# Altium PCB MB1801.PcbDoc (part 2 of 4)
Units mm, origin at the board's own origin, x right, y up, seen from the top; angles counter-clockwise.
Board outline 70.1 x 57.1 mm, 4 copper layers (Top Layer, Signal Layer 1, Signal Layer 2, Bottom Layer), stack 1.614 mm thick; 219 components, 166 nets, 1002 pads, 473 vias.
Unrouted connection lines stored in the file: 2.
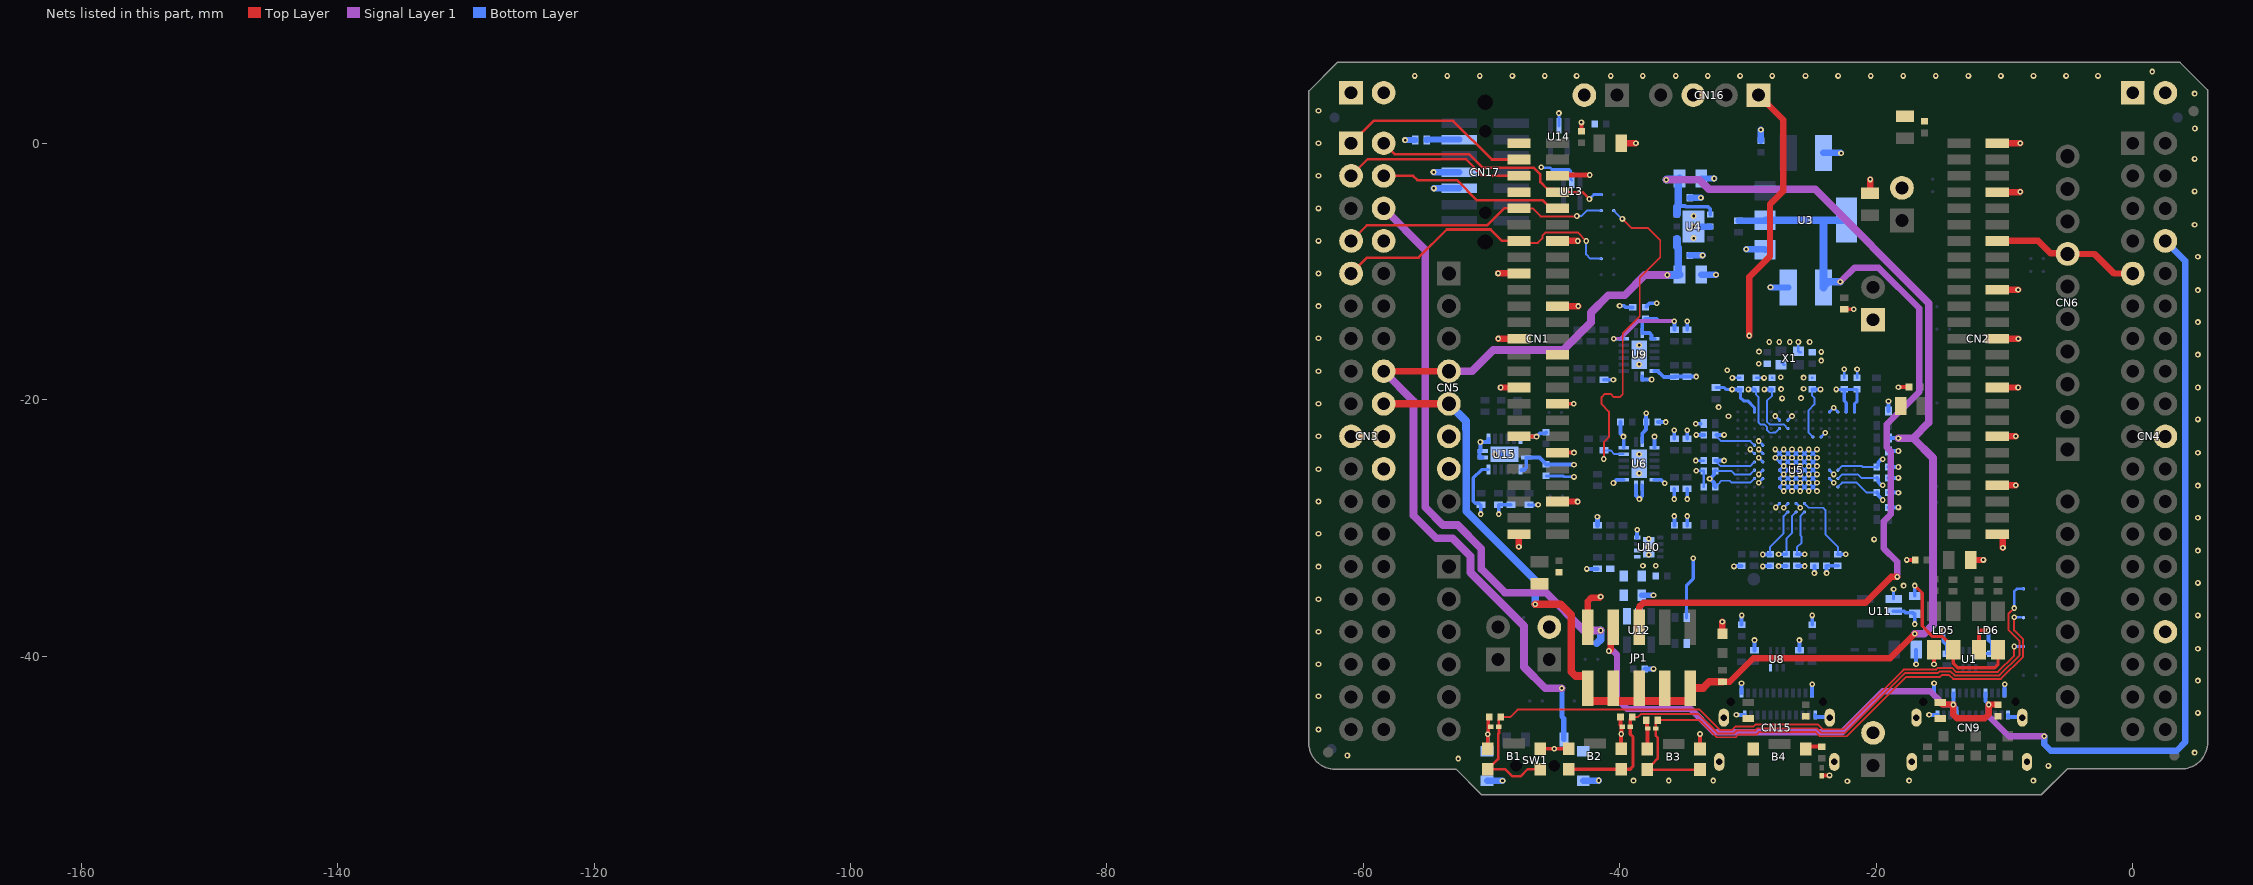
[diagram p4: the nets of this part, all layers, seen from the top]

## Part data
1 ?: library part MCD-01965
B1 B2 B3 B4: library part MCD-01485, "Microminiature Tact Switch for SMT - KMR 2 Series - 1.9 mm height", Manufacturer=C&K, Manufacturer_Part_Number=KMR231GLFS
C1 C2 C3 C4 C5 C6 C19 C21: library part MCD-01550, "Capacitor, MLCC, 1uF, 16V, X5R, +/-10%, 0805, T=0.85mm", Manufacturer=YAGEO, Manufacturer_Part_Number=CC0805KRX5R7BB105, Package=0805
C7 C8 C9 C10 C11 C18 C20 C22 C35 C58: library part MCD-02355, "Capacitor, MLCC, 100nF, 25V, X7R, +/-10%, 0402, T=0.5mm", Manufacturer=WALSIN, Manufacturer_Part_Number=0402B104K250CT, Package=0402
C12 C13 C14 C26 C27 C36: library part MCD-02198, "Capacitor, MLCC, 10nF, 50V, X7R, +/-10%, 0402, T=0.5mm", Manufacturer=YAGEO, Manufacturer_Part_Number=CC0402KRX7R9BB103, Package=0402
C15 C23: library part MCD-00205, "Capacitor, MLCC, 100pF, 50V, NPO, +/-5%, 0402, T=0.5mm", Manufacturer=YAGEO, Manufacturer_Part_Number=CC0402JRNPO9BN101, Package=0402
C16 C17: library part MCD-00324, "Capacitor, Tantalum, 10uF, 25V, 2R5, +/-10%, Type_B (3528 metric), T=1.9mm", Manufacturer=AVX, Manufacturer_Part_Number=TAJB106K025RNJ, Package="3528 (metric)"
C24 C25 C30 C31 C32 C37 C38 C39 C40 C41 C42 C43 C44 C45 C46 C47 C48 C49 C50 C51 C52 C53 C60 C61 C62: library part MCD-00006, "Capacitor, MLCC, 100nF, 16V, X7R, 10%, 0402, T=0.5mm", Alternate_Manufacturer=MURATA, Alternate_Manufacturer_Part_Number=GCM155R71C104KA55D, Manufacturer=YAGEO, Manufacturer_Part_Number=CC0402KRX7R7BB104, Package=C0402
C28 C29: library part MCD-01774, "Capacitor, MLCC, 2.7pF, 50V, NPO, +/-0.1pF, 0402, T=0.5mm", Manufacturer=YAGEO, Manufacturer_Part_Number=CC0402BRNPO9BN2R7, Package=0402
C33 C56 C57: library part MCD-02606, "Capacitor, MLCC, 2.2uF, 6.3V, X5R, +/-10%, 0402, T=0.5mm", Manufacturer=YAGEO, Manufacturer_Part_Number=CC0402KRX5R5BB225, Package=0402
C34 C55 C59: library part MCD-00099, "Capacitor, MLCC, 10uF, 10V, X5R, +/-10%, 0603, T=0.8mm", Manufacturer=MURATA, Manufacturer_Part_Number=GRM188R61A106KE69D, Package=0603
C54: library part MCD-02372, "Capacitor, MLCC, 2.2uF, 25V, X7R, +/-10%, 0805, T=1,25mm", Alternate_Manufacturer=N/A, Manufacturer=MURATA, Manufacturer_Part_Number=GRM21BR71E225KE11L, Package=C0805
CN1 CN2: library part MCD-02705, "Socket, 25x2, 1.27mm, VR, SMD, T=2.29mm", Manufacturer=SAMTEC
CN3 CN4: library part MCD-00213, "Header, 19x2, 2.54mm, VR, TH, T=5.84mm/10.16mm", Manufacturer=SAMTEC, Manufacturer_Part_Number=TSW-119-09-G-D
CN5 CN8: library part MCD-01743, "Socket, 8x1, 2.54mm, VR, TH, T=8.51/2.64mm", Manufacturer=SAMTEC, Manufacturer_Part_Number=SSW-108-01-G-S
CN6: library part MCD-02080, "Socket, 10x1, 2.54mm, VR, TH, T=8.51/2.64mm", Manufacturer=SAMTEC, Manufacturer_Part_Number=SSW-110-01-G-S
CN7: library part MCD-02079, "Socket, 6x1, 2.54mm, VR, TH, T=8.51/2.64mm", Manufacturer=SAMTEC, Manufacturer_Part_Number=SSW-106-01-G-S
CN9 CN15: library part MCD-03232, "USB_TypeC, 24 pins, RA, SMD, T=2.96mm", Manufacturer="AMPHENOL ICC", Manufacturer_Part_Number=12401826E412A
CN10 CN11 CN12 CN13 CN14: library part MCD-00032, "Header, 2x1, 2.54mm, VR, TH, T=5.84mm/2.54mm", Manufacturer=SAMTEC, Manufacturer_Part_Number=TSW-102-07-G-S
CN16: library part MCD-00029, "Header, 4x1, 2,54mm, VR, TH, Height 5.84mm/2.54mm", Manufacturer=SAMTEC, Manufacturer_Part_Number=TSW-104-07-x-S
CN17: library part MCD-01226, "Header, 5x2, 1.27mm, VR, SMD, T=5.97mm/3.05mm", Manufacturer=SAMTEC, Manufacturer_Part_Number=FTSH-105-01-L-DV-K
D1: library part MCD-01677, "Small signal Schottky diodes", Manufacturer=STMICROELECTRONICS, Manufacturer_HQ_COO=EU, Manufacturer_Part_Number=BAT54KFILM, Package=SOD-523
HW1: library part MCD-02189, "Sticker product 25x5 mm", Manufacturer=N/A
HW2: library part MCD-02190, "Sticker board 25x5 mm", Manufacturer=N/A
JP1: library part MCD-03317, "Header, 10x2, 2,00mm, h=7,04mm, VR, SMD", Manufacturer=SAMTEC, Manufacturer_Part_Number=TMM-105-06-T-D-SM
JP2: library part MCD-01904, "Header, 2x1, 2.54mm, VR, TH, T=5.84mm/2.54mm", Manufacturer=SAMTEC, Manufacturer_Part_Number=TSW-102-07-G-S
JP3 JP4: library part MCD-00045, "Header, 2x1, 2,54mm, VR, TH, Height 5.84mm/2.54mm", Alternate_Manufacturer="JIUBABA; LIANYI", Alternate_Manufacturer_Part_Number=313102S111116;313102S111116, Manufacturer=SAMTEC, Manufacturer_Part_Number=TSW-102-07-G-S
LD1: library part MCD-00584, "LED Blue, 0603 SMD, 3.3 V Forward Voltage", Manufacturer=VISHAY, Manufacturer_Part_Number=VLMB1300-GS08, Package="LED 0603"
LD2 LD4: library part MCD-00589, "LED Green, 0603 SMD, Fw Voltage = 2.8V - 3.6V", Manufacturer=VISHAY, Manufacturer_Part_Number=VLMTG1300-GS08, Package="LED 0603"
LD3: library part MCD-00587, "LED Red, 0603 SMD, 2V Forward Voltage", Manufacturer=VISHAY, Manufacturer_Part_Number=VLMS1300-GS08, Package="LED 0603"
LD5 LD6: library part MCD-02631, "LED Bicolor, Green/Red, 2V, 20mA,  4-PLCC", Manufacturer="WURTH ELEKTRONIK", Manufacturer_Part_Number=150141SV73110, Package=4-PLCC
R1: library part MCD-00061, "Resistor, 1K, 0402, +/-1%,1/16W", Manufacturer=YAGEO, Manufacturer_Part_Number=RC0402FR-071KL, Package=0402
R2 R15 R16 R17 R18 R19 R24 R25 R26 R27 R28 R41 R59 R60 R61 R62 R63 R64 R65 R66 R67: library part MCD-00059, "Resistor,100K,0402,1%,1/16W", Alternate_Manufacturer=YAGEO, Alternate_Manufacturer_Part_Number=RT0402FRE07100KL, Manufacturer_Part_Number=RC0402FR-07100KL, Package=R0402
R6 R7 R8: library part MCD-00507, "Resistor, 680R, 0402, +/-1%, 1/16W", Manufacturer=YAGEO, Manufacturer_Part_Number=RC0402FR-07680RL, Package=0402
R11 R12: library part MCD-00333, "Resistor, 5K1, 0402, +/-1%, 1/16W", Manufacturer=YAGEO, Manufacturer_Part_Number=RC0402FR-075K1L, Package=0402
R13: library part MCD-00068, "Resistor, 1K5, 0402, +/-1%, 1/16W", Manufacturer=YAGEO, Manufacturer_Part_Number=RC0402FR-071K5L, Package=0402
R14 R23 R36 R42: library part MCD-00333, "Resistor, 5K1, 0402, +/-1%, 1/16W", Alternate_Manufacturer=N/A, Manufacturer=YAGEO, Manufacturer_Part_Number=RC0402FR-075K1L, Package=0402
R20 R22 R46 R47 R52 R53: library part MCD-00059, "Resistor, 100K, 0402, +/-1%, 1/16W", Manufacturer=YAGEO, Manufacturer_Part_Number=RC0402FR-07100KL, Package=0402
R21 R29 R55 R57: library part MCD-00052, "Resistor, 0R, 0402, +/-5%, 1/16W", Manufacturer=YAGEO, Manufacturer_Part_Number=RC0402JR-070RL, Package=0402
R30: library part MCD-00185, "Resistor,3K,0402,1%,1/16W", Manufacturer=YAGEO, Manufacturer_Part_Number=RC0402FR-073KL, Package=R0402
R31 R33 R38 R39: library part MCD-00053, "Resistor,10K,0402,1%,1/16W", Manufacturer=YAGEO, Manufacturer_Part_Number=RC0402FR-0710KL, Package=R0402
R32 R34 R35 R37: library part MCD-00481, "Resistor,47R,0402,1%,1/16W", Manufacturer=YAGEO, Manufacturer_Part_Number=RC0402FR-0747RL, Package=R0402
R40: library part MCD-00185, "Resistor, 3K, 0402, +/-1%, 1/16W", Manufacturer=YAGEO, Manufacturer_Part_Number=RC0402FR-073KL, Package=0402
R43: library part MCD-00409, "Resistor, 1K8, 0402, +/-1%, 1/16W", Manufacturer=YAGEO, Manufacturer_Part_Number=RC0402FR-071K8L, Package=0402
R44: library part MCD-00381, "Resistor, 1K3, 0402, +/-1%, 1/16W", Manufacturer=YAGEO, Manufacturer_Part_Number=RC0402FR-071K3L, Package=0402
R45: library part MCD-02455, "Resistor, 3K9, 0402, +/-1%, 1/16W, +/-100ppm/°C", Manufacturer=YAGEO, Manufacturer_Part_Number=RC0402FR-073K9L, Package=0402
R48 R49: library part MCD-02665, "Resistor, 1K, 0402, +/-0.1%, 1/16W, +/-25ppm/°C", Manufacturer=YAGEO, Manufacturer_Part_Number=RT0402BRD071KL, Package=0402
R50 R51: library part MCD-00062, "Resistor, 330R, 0402, +/-1%, 1/16W", Manufacturer=YAGEO, Manufacturer_Part_Number=RC0402FR-07330RL, Package=0402
R54: library part MCD-00067, "Resistor, 100R, 0402, +/- 1%, 1/16W", Manufacturer=YAGEO, Manufacturer_Part_Number=RC0402FR-07100RL, Package=0402
R56 R58: library part MCD-00455, "Resistor, 33R, 0402, +/-1%, 1/16W", Manufacturer=YAGEO, Manufacturer_Part_Number=RC0402FR-0733RL, Package=0402
SB1 SB2 SB3 SB4 SB5 SB6 SB7 SB8 SB9 SB10 SB11 SB12 SB13 SB14 SB15 SB16 SB17 SB18 SB19 SB20 SB21 SB22 SB23 SB24 SB25 SB26 SB27 SB28 SB29 SB30 SB33: library part MCD-01618, "Solder Bridge 0402 ON", Manufacturer=YAGEO, Manufacturer_Part_Number=RC0402JR-070RL, Package=SB0402
SW1: library part MCD-03571, "Slide switch, 3x1, 1.5mm, RA, SMT, T=1.65mm", Manufacturer=C&K, Manufacturer_Part_Number=PCM12SMTR, Package=NA
TP1: library part MCD-00074, "Test Point 1mm", Manufacturer=n/a
U1 U8: library part MCD-00649, "Common mode filter with ESD protection for USB 2.0 interface", Manufacturer=STMICROELECTRONICS, Manufacturer_HQ_COO=EU
U2: library part MCD-01207, "High power Transient voltage suppressor:25V/35A EOS and ESD transients protection.", Manufacturer=STMICROELECTRONICS, Manufacturer_HQ_COO=EU, Manufacturer_Part_Number=ESDA25P35-1U1M, Package=QFN1610
U3: library part MCD-00088, "IC REG LDO 5V 0.8A SOT223", Manufacturer=STMICROELECTRONICS, Manufacturer_HQ_COO=EU, Package=SOT-223
U4: library part MCD-00215, "Low quiescent current and low noise voltage regulators", Manufacturer=STMICROELECTRONICS, Manufacturer_HQ_COO=EU, Package="DFN6 3x3mm"
U5: library part MCD-02706, "MCU, ARM Cortex-M7 32-bit, 512KB Flash, 276KB RAM, With Crypto", Manufacturer=STMICROELECTRONICS, Manufacturer_Part_Number=STM32F723IEK6, Package=BGA-176
U6 U9 U15: library part MCD-01945, "4-bit dual supply translating transceiver with configurable voltage translation; 3-state", Alternate_Manufacturer=N/A, Manufacturer=NEXPERIA, Manufacturer_Part_Number=74AVC4TD245BQ,115, Package=DHVQFN16
U7: library part MCD-01207, "High power Transient voltage suppressor:25V/35A EOS and ESD transients protection.", Manufacturer=STMICROELECTRONICS, Manufacturer_Part_Number=ESDA25P35-1U1M, Package=QFN1610
U10: library part MCD-02532, "IC, 2V7 to 18V, 4A, 34mR, eFuse with fast overvoltage protection", Manufacturer="TEXAS INSTRUMENTS", Package=WSON-8
U11: library part MCD-02514, "LDO, 3.3V, 300mA, High input voltage: 2.5V to 28V, SOT23-5L", Alternate_Manufacturer=N/A, Manufacturer=STMICROELECTRONICS, Package=SOT23-5L
U12: library part MCD-00159, "500mA, Enhanced single channel power switches with active high enable pin", Manufacturer=STMICROELECTRONICS, Manufacturer_HQ_COO=EU
U13 U14: library part MCD-00136, "Dual Transil array for ESD protection", Manufacturer=STMICROELECTRONICS, Manufacturer_HQ_COO=EU
U16 U17 U18 U19: library part MCD-00170, "ESD protection 6V1", Manufacturer=STMICROELECTRONICS, Manufacturer_HQ_COO=EU, Manufacturer_Part_Number=ESDALC6V1-1U2
X1: library part MCD-01036, "Crystal, 24MHz, 6pF, +/-20ppm, 80R, 2x1.6mm", Manufacturer=NDK, Manufacturer_Part_Number=NX2016SA-24MHZ-EXS00A-CS10820, Package=2x1.6mm

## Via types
v1: diameter 0.45, hole 0.2, Top Layer to Bottom Layer, tented both sides, 473 vias

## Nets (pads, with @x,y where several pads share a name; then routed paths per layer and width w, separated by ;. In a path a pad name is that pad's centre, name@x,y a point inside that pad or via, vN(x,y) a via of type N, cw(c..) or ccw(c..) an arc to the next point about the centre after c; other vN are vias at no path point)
3V3: C21.2 C22.2 CN3.16 CN5.4 SB19.2 SW1.1 U4.4 | length 65.4
  Top Layer w0.5: CN3.16@-58.42,-17.78 CN5.4@-53.34,-17.78
  Signal Layer 1 w0.6: CN3.16@-58.42,-17.78 -56.1,-20.1 -56.1,-29.025 -54.325,-30.8 -53.05,-30.8 -51.65,-32.2 -51.65,-33.475 -47.475,-37.65 -47.475,-40.85 -45.825,-42.5 v1(-44.525,-42.5) ; CN5.4@-53.34,-17.78 -51.53,-17.78 -49.875,-16.125 -44.4,-16.125 -42.25,-13.975 -42.25,-13.2 -40.9,-11.85 -39.625,-11.85 -38.05,-10.275 v1(-36.3,-10.275)
  Bottom Layer w0.4: v1(-44.525,-42.5) SB19.2@-44.525,-43.5 -44.525,-44.7 -44.375,-44.85 -44.375,-46.483 SW1.1@-44.35,-46.509
  Bottom Layer w0.6: v1(-36.3,-10.275) -35.5,-10.275 -35.475,-10.25 C21.2@-35.35,-10.25 ; U4.4@-35.55,-7.45 -35.55,-8.075 -35.45,-8.175 C22.2@-35.45,-8.75 C21.2@-35.45,-10.15
3V3_STLK: C24.2 C30.2 C37.1 C38.1 C39.1 C40.1 C41.1 C42.1 C43.1 C44.1 C45.1 C46.1 C47.1 C48.1 C49.1 C50.1 C51.1 C52.1 C53.1 C55.2 C60.2 CN16.1 JP4.1 LD5.4 LD6.4 R2.1 R15.2 R16.2 R17.2 R24.1 R25.2 R26.2 R27.2 R39.2 R52.1 R61.2 R62.2 R63.2 R64.2 U5.C1 U5.C5 U5.C6 U5.C7 U5.C8 U5.C9 U5.F3 U5.G3 U5.G13 U5.H13 U5.J12 U5.J13 U5.K4 U5.N8 U5.N9 U5.N10 U5.P1 U5.R1 U6.1 U6.2 U9.1 U9.2 U9.7 U9.15 U11.1 U15.1 U15.2 U15.7 | length 146.3
  Top Layer w0.254: v1(-17,-34.5) -16.425,-35.075 -16.425,-37.65 -15.6,-38.475 -14.825,-38.475 -14.423,-38.877 -14,-39.3 LD5.4@-14,-39.5 -14,-40.549 -13.651,-40.898 -10.773,-40.898 -10.5,-40.625 LD6.4@-10.5,-39.5
  Top Layer w0.5: v1(-29.9,-15) -29.9,-10.425 -28.288,-8.813 -28.288,-4.763 -27.25,-3.725 -27.25,1.825 CN16.1@-29.2,3.775
  Signal Layer 1 w0.3: v1(-40.475,-15.25) -39.95,-15.25 -38.575,-13.875 v1(-35.75,-13.875)
  Bottom Layer w0.15: C52.1@-32.55,-25.55 -31.325,-25.55 -31.05,-25.825 -29.825,-25.825 U5.C8@-29.5,-25.5 ; C51.1@-32.5,-24.825 -32.15,-25.175 -29.825,-25.175 U5.C7@-29.5,-24.85 ; C53.1@-32.45,-26.675 -32.37,-26.595 -32.345,-26.595 -32.075,-26.325 -31.425,-26.325 -31.325,-26.425 -31.28,-26.47 -30.73,-26.47 -30.725,-26.475 -29.825,-26.475 U5.C9@-29.5,-26.15 ; C50.1@-32.45,-22.875 -32.37,-22.955 -32.1,-23.225 -29.825,-23.225 U5.C5@-29.5,-23.55 ; v1(-29.825,-23.875) U5.C6@-29.5,-24.2 ; C48.1@-29.375,-19.2 -29.375,-19.6 -29.175,-19.8 -29.175,-21.8 -29.05,-21.925 -28.722,-21.925 -28.525,-22.122 -28.525,-22.375 -28.52,-22.38 -28.52,-22.383 -28.323,-22.58 -28.075,-22.58 ; C40.1@-28.275,-32.025 -28.275,-31.475 -27.225,-30.425 -27.225,-29.075 U5.G13@-26.9,-28.75 ; C47.1@-28.125,-19.2 -28.125,-19.675 -28.525,-20.075 -28.525,-21.4 -28.53,-21.405 -28.53,-21.723 -28.328,-21.925 -27.225,-21.925 U5.G3@-26.9,-22.25 ; -28.075,-22.575 -27.875,-22.575 U5.F3@-27.55,-22.25 ; C39.1@-27,-32.025 -27,-30.825 -26.58,-30.405 -26.58,-29.08 U5.H13@-26.25,-28.75 ; C37.1@-26.2,-32.025 -26.2,-31.525 -25.825,-31.15 -25.825,-30.675 -25.925,-30.575 -25.925,-29.075 U5.J13@-25.6,-28.75 ; U5.J12@-25.6,-28.1 -25.275,-28.425 -24.15,-28.425 -23.97,-28.605 -23.97,-30.505 -23,-31.475 C38.1@-23,-32 ; C46.1@-25,-19.2 -25,-19.675 -24.825,-19.85 -24.825,-20.372 -25.28,-20.827 -25.28,-22.57 U5.K4@-24.95,-22.9 ; U5.N10@-23,-26.8 -22.675,-26.475 -21.525,-26.475 -20.75,-27.25 C41.1@-20,-27.25 ; U5.N9@-23,-26.15 -22.67,-25.82 -21.625,-25.82 -21.615,-25.83 -21.445,-25.83 -21.325,-25.95 -21.175,-26.1 C42.1@-19.95,-26.1 ; U5.N8@-23,-25.5 -22.68,-25.18 -22.31,-25.18 -22.3,-25.17 -21.13,-25.17 -21.05,-25.25 C43.1@-19.95,-25.25
  Bottom Layer w0.254: v1(-50.85,-28.921) -50.85,-28.225 -51.003,-28.072 -51.276,-28.072 -51.427,-27.921 -51.427,-26.102 -50.775,-25.45 U15.7@-50.25,-25.45 ; v1(-49.45,-28.925) R63.2@-49.45,-28.2 ; R63.2@-49.4,-28.2 R62.2@-48.5,-28.2 ; R61.2@-47.1,-28.2 -47.096,-28.204 -46.379,-28.204 v1(-46.375,-28.2) ; v1(-35.75,-27.75) R17.2@-35.75,-26.95 ; R52.1@-34.8,-37 -34.8,-34.475 -34.275,-33.95 v1(-34.275,-32.375) ; v1(-34.75,-27.75) R16.2@-34.75,-26.95 ; R15.2@-34.75,-23.05 v1(-34.75,-22.375) ; R2.1@-32.5,-19.05 -31.875,-19.05 -31.725,-19.2 v1(-31.25,-19.2) ; C49.1@-30.6,-19.2 -30.6,-19.85 -30.35,-20.1 -30.025,-20.1 -29.5,-20.625 U5.C1@-29.5,-20.95 ; v1@-27.6,-32.05 C39.1@-27,-32.05 ; v1(-23.125,-19.2) C45.1@-22.5,-19.2 ; U5.P1@-22.35,-20.95 -22.35,-20.25 -22.5,-20.1 C45.1@-22.5,-19.2 ; U5.R1@-21.7,-20.95 -21.7,-20.325 -21.5,-20.125 C44.1@-21.5,-19.2 C45.1@-22.5,-19.2 ; U11.1@-18.65,-35.55 v1(-18.65,-34.775) ; C55.2@-17,-35.3 v1(-17,-34.5)
  Bottom Layer w0.3: U15.2@-47.675,-25.475 -47.476,-25.475 -47.3,-25.299 U15.1@-47.3,-24.5 -46.275,-24.5 C60.2@-45.88,-24.895 ; C60.2@-45.75,-25.05 -43.6,-25.05 v1(-43.575,-25.075) ; v1(-40.475,-15.25) U9.15@-39.7,-15.25 ; U6.1@-38.25,-23.3 -38.25,-22.625 -37.95,-22.325 C24.2@-37.95,-21.75 v1(-37.95,-21.05) ; U6.2@-37.3,-23.75 v1(-37.3,-22.875) ; U9.7@-37.3,-17.75 -37.05,-17.75 -36.575,-18.225 R27.2@-35.7,-18.225 ; U9.2@-37.3,-15.25 -37.524,-15.25 -37.524,-14.976 -37.7,-14.8 U9.1@-38.25,-14.8 -38.25,-13.95 -38.13,-13.83 -38.13,-13.805 -38.025,-13.7 -37.125,-13.7 -36.95,-13.875 v1(-35.75,-13.875) R24.1@-35.75,-14.55 ; R27.2@-35.75,-18.2 v1@-34.063,-18.2 ; R25.2@-34.75,-14.55 v1(-34.75,-13.875) ; v1(-34.075,-21.875) R39.2@-33.7,-21.875 ; v1(-33,-26.175) v1@-32.975,-26.175 ; C53.1@-32.55,-26.8 -32.655,-26.695 -32.655,-26.47 -32.88,-26.245 -32.889,-26.245 -32.959,-26.175 v1@-32.975,-26.175 ; C52.1@-32.55,-25.5 -32.655,-25.605 -32.655,-25.855 v1@-32.975,-26.175 ; C51.1@-32.55,-24.75 v1(-31.875,-24.75) ; C50.1@-32.45,-22.75 v1(-31.875,-22.75) ; v1(-31.25,-19.2) C49.1@-30.6,-19.2 ; v1(-29.975,-19.2) C48.1@-29.5,-19.2 ; v1(-28.85,-32.075) -28.838,-32.063 -28.263,-32.063 C40.1@-28.25,-32.05 ; v1(-28.725,-19.2) C47.1@-28.125,-19.2 ; C37.1@-26.2,-32.05 v1(-25.575,-32.05) ; C46.1@-25,-19.2 v1(-24.35,-19.2) ; C38.1@-23,-32.05 v1(-22.375,-32.05) ; C41.1@-19.95,-27.25 -19.845,-27.355 -19.845,-27.48 v1(-19.5,-27.825) ; C42.1@-19.95,-26.1 -19.845,-26.205 -19.845,-26.424 -19.623,-26.646 -19.529,-26.646 v1(-19.5,-26.675) ; C43.1@-19.95,-25.25 -19.845,-25.145 -19.845,-24.901 -19.623,-24.679 -19.529,-24.679 v1(-19.5,-24.65)
  other v1: -17.875,-34.5 -27.625,-32.05 -34.05,-18.2
5V: C19.2 C20.2 CN3.18 CN5.5 JP1.1 JP1.3 JP1.5 JP1.7 JP1.9 R13.2 R36.2 U4.1 U4.6 | length 127.2
  Top Layer w0.5: R13.2@-32,-42 -31.995,-41.995 -31.42,-41.995 -29.6,-40.175 -18.925,-40.175 v1(-17,-38.25)
  Top Layer w0.6: CN3.18@-58.42,-20.32 CN5.5@-53.34,-20.32 ; v1(-46.6,-35.95) -44.625,-35.95 -43.8,-36.775 -43.8,-41.204 -43.449,-41.556 -42.645,-41.556 -42.5,-41.701 -42.5,-43.361 -42.355,-43.506 -40.5,-43.506 -38.645,-43.506 JP1.5@-38.5,-43.361 ; JP1.1@-42.5,-43.301 JP1.1@-42.5,-42.5 ; JP1.3@-40.5,-43.43 JP1.3@-40.5,-42.5 ; JP1.5@-38.5,-43.301 JP1.5@-38.5,-43.361 ; JP1.5@-38.5,-43.106 JP1.5@-38.5,-42.5 ; JP1.7@-36.5,-42.5 JP1.7@-36.5,-43.361 ; R13.2@-32,-42 -33.025,-42 -33.506,-42.481 -34.481,-42.481 JP1.9@-34.5,-42.5 -34.5,-43.361 -34.645,-43.506 -36.355,-43.506 JP1.7@-36.5,-43.361 ; JP1.5@-38.5,-43.361 -38.355,-43.506 -36.645,-43.506 JP1.7@-36.5,-43.361
  Signal Layer 1 w0.6: v1(-36.375,-2.85) -33.8,-2.85 -33.05,-3.6 -24.775,-3.6 -15.9,-12.475 -15.9,-21.775 -17.125,-23 ; v1(-18.275,-23) -17.125,-23 ; v1(-17,-38.25) -16.275,-38.25 -15.575,-37.55 -15.575,-24.55 -17.125,-23
  Bottom Layer w0.3: -35.55,-4.975 -35.475,-4.9 -34.9,-4.9 -34.85,-4.95 -33.126,-4.95 -32.95,-5.126 U4.1@-32.95,-5.55 ; R36.2@-19.05,-23 v1(-18.275,-23)
  Bottom Layer w0.6: CN5.5@-53.34,-20.32 -52,-21.66 -52,-22.291 -51.99,-22.301 -51.99,-28.701 -46.6,-34.091 v1(-46.6,-35.95) ; v1(-36.375,-2.85) -36.337,-2.812 C19.2@-35.412,-2.812 ; U4.6@-35.55,-5.55 -35.55,-4.975 ; -35.475,-4.9 -35.45,-4.875 C20.2@-35.45,-4.25 -35.45,-2.85 C19.2@-35.412,-2.812 ; C19.2@-35.35,-2.75 C19.2@-35.412,-2.812
5V_EXT: CN3.6 SB33.1 | length 44.4
  Signal Layer 1 w0.6: CN3.6@-58.42,-5.08 -55.175,-8.325 -55.175,-28.4 -53.8,-29.775 -52.65,-29.775 -50.8,-31.625 -50.8,-33.2 -48.95,-35.05 -45.75,-35.05 -42.8,-38 v1(-41.5,-38)
  Bottom Layer w0.6: SB33.1@-41.8,-39 -41.5,-38.7 v1(-41.5,-38)
5V_INT: C17.1 JP1.6 R1.2 U3.2 U3.4 | length 68.5
  Top Layer w0.5: JP1.6@-38.5,-37.75 -38.5,-36.175 -38.175,-35.85 -20.85,-35.85 -18.825,-33.825 v1(-18.375,-33.825)
  Signal Layer 1 w0.5: v1(-22.8,-10.8) -21.7,-9.7 -19.825,-9.7 -16.65,-12.875 -16.65,-19.4 -19.175,-21.925 -19.175,-23.725 -18.875,-24.025 -18.875,-28.925 -19.425,-29.475 -19.425,-31.6 -18.375,-32.65 v1@-18.375,-33.8
  Bottom Layer w0.5: R1.2@-30.75,-6.05 U3.2@-28.7,-6.05 ; U3.2@-28.65,-6.05 U3.2@-28.6,-6
  Bottom Layer w0.6: U3.2@-28.6,-6 -24.125,-6 ; C17.1@-24.125,-11.25 C17.1@-24.125,-11.176 ; v1(-22.8,-10.8) -23.75,-10.8 -24.125,-11.175 C17.1@-24.125,-11.176 ; U3.4@-22.325,-6 -24.125,-6 ; C17.1@-24.125,-11.176 -24.125,-6
5V_STLK: C34.2 C59.2 JP1.2 R40.1 U10.5 U10.6 U12.1 | length 3.2
  Top Layer w0.5: JP1.2@-42.5,-37.75 -42.5,-35.725 -42.207,-35.432 -41.557,-35.432 v1(-41.5,-35.375)
5V_USB_MCU: C15.2 CN4.8 CN9.A4 CN9.A9 CN9.B4 CN9.B9 JP1.4 U2.1 | length 102.9
  Top Layer w0.5: v1(-40.85,-39.6) -40.695,-39.445 -40.695,-37.945 JP1.4@-40.5,-37.75 ; U2.1@-15,-43.625 -14.875,-43.75 -14.54,-43.75 -14.515,-43.775 v1(-14,-43.775) -14,-44.557 -13.707,-44.85 -11.55,-44.85 -11.225,-44.525 v1@-11.225,-43.8 ; v1(-11.225,-43.775) C15.2@-10.534,-43.775
  Signal Layer 1 w0.5: v1(-40.85,-39.6) -40.518,-39.6 -40.225,-39.893 -40.225,-43.325 -39.425,-44.125 -34.475,-44.125 -32.675,-45.925 -22.675,-45.925 -19.5,-42.75 -15.8,-42.75 -14.775,-43.775 v1(-14,-43.775) ; v1(-11.225,-43.775) -11.225,-44.7 -9.675,-46.25 v1(-6.9,-46.25)
  Bottom Layer w0.3: CN9.A9@-13.99,-42.89 -13.99,-43.765 v1(-14,-43.775) -13.991,-43.775 -13.74,-44.026 CN9.B4@-13.74,-44.59 ; CN9.A4@-11.49,-42.89 -11.49,-43.522 -11.237,-43.775 v1(-11.225,-43.775) -11.24,-43.79 CN9.B9@-11.24,-44.59
  Bottom Layer w0.5: v1@-6.899,-46.251 -6.899,-46.876 -6.4,-47.375 3.425,-47.375 4.1,-46.7 4.1,-9.18 CN4.8@2.54,-7.62
B1: B1.2 B1.4 C12.2 SB2.2 U16.1 | length 54.4
  Top Layer w0.15: C12.2@-49.3,-44.75 -48.55,-44.75 -47.975,-44.175 -33.775,-44.175 -32.175,-45.775 -31.273,-45.775 -30.998,-45.5 -29.582,-45.5 -29.407,-45.325 -24.55,-45.325 -24.175,-45.7 -22.528,-45.7 -17.878,-41.05 -15.324,-41.05 -15.199,-40.925 -14.086,-40.925 -13.786,-41.225 -10.514,-41.225 -9.25,-39.961 v1(-9.25,-39.25)
  Top Layer w0.2: C12.2@-49.3,-44.75 -49.438,-44.887 U16.1@-49.438,-45.5 -49.425,-45.513 -49.425,-46 -49.5,-46.075 -49.5,-48.022 -49.9,-48.422 -49.95,-48.422 -50.3,-48.772 B1.4@-50.3,-48.822 -50.297,-48.825 -48.925,-48.825 -48.375,-49.375 -47.75,-49.375 -47.197,-48.822 B1.2@-46.2,-48.822
  Bottom Layer w0.2: v1(-9.25,-39.25) SB2.2@-8.525,-39.25
B2: B2.2 B2.4 C13.2 SB4.2 U17.1 | length 49.4
  Top Layer w0.15: C13.2@-39.05,-44.75 -38.6,-44.75 -38.35,-44.5 -33.874,-44.5 -33.499,-44.875 -33.496,-44.875 -32.775,-45.596 -32.321,-46.05 -31.124,-46.05 -30.874,-45.8 -29.458,-45.8 -29.283,-45.625 -24.639,-45.625 -24.289,-45.975 -22.414,-45.975 -17.764,-41.325 -15.21,-41.325 -15.085,-41.2 -14.2,-41.2 -13.9,-41.5 -10.4,-41.5 -8.825,-39.925 -8.825,-38.825 -9.675,-37.975 -9.675,-36.675 v1(-9.25,-36.25)
  Top Layer w0.254: B2.4@-44,-48.822 -39.928,-48.822 B2.2@-39.925,-48.825 ; B2.2@-39.9,-48.822 -39.197,-48.822 -38.975,-48.6 -38.975,-46.3 -39.188,-46.087 U17.1@-39.188,-45.5 -39.188,-44.912 -39.05,-44.775 C13.2@-39.05,-44.75
  Bottom Layer w0.2: v1(-9.25,-36.25) -9.25,-34.975 -9.025,-34.75 SB4.2@-8.525,-34.75
B3: B3.2 B3.4 C14.2 SB6.2 U18.1 | length 44.5
  Top Layer w0.15: C14.2@-37.05,-45 -37.025,-44.975 -33.824,-44.975 -33.649,-45.15 -33.61,-45.15 -33.05,-45.71 -32.435,-46.325 -30.974,-46.325 -30.749,-46.1 -29.333,-46.1 -29.158,-45.925 -24.728,-45.925 -24.403,-46.25 -22.3,-46.25 -17.675,-41.625 -15.047,-41.625 -14.897,-41.475 -14.314,-41.475 -14.014,-41.775 -10.286,-41.775 -8.55,-40.039 -8.55,-38.7 -9.25,-38 v1(-9.25,-36.975)
  Top Layer w0.2: C14.2@-37.05,-45 -37.188,-45.137 U18.1@-37.188,-45.65 -37.2,-45.662 -37.2,-46.2 -37.05,-46.35 -37.05,-48 -37.5,-48.45 -37.85,-48.8 B3.4@-37.85,-48.85 B3.2@-33.75,-48.85
  Bottom Layer w0.2: v1(-9.25,-36.975) -8.725,-36.975
DBG_BOOTLOADER: R60.1 SB28.2 U6.14 | length 27.4
  Top Layer w0.15: v1(-41.25,-24.625) -41.25,-23.325 -40.85,-22.925 -40.85,-20.925 -41.425,-20.35 -41.425,-19.8 -41.175,-19.55 -40.725,-19.55 -40.475,-19.8 -40,-19.8 -39.775,-19.575 -39.775,-15.175 -39.775,-14.825 -38.45,-13.5 -38.45,-10.975 -38.45,-10.487 -36.85,-8.887 -36.85,-8.675 -36.85,-7.575 -37.825,-6.6 -39.1,-6.6 v1(-39.8,-5.9)
  Bottom Layer w0.15: R60.1@-41.275,-23.95 -40.725,-23.95 -40.425,-24.25 U6.14@-39.7,-24.25 ; v1(-41.25,-24.625) R60.1@-41.25,-23.95 ; SB28.2@-40.475,-5.25 -40.475,-5.278 -39.853,-5.9 v1(-39.8,-5.9)
GND: B1.1 B1.3 B2.1 B2.3 B3.1 B3.3 B4.1 B4.3 C1.1 C2.1 C3.1 C4.1 C5.1 C6.1 C7.1 C8.1 C9.1 C10.1 C11.1 C12.1 C13.1 C14.1 C15.1 C16.2 C17.2 C18.1 C19.1 C20.1 C21.1 C22.1 C23.2 C24.1 C25.2 C26.2 C27.2 C28.1 C29.2 C30.1 C31.2 C32.1 C33.1 C34.1 C35.1 C36.1 C37.2 C38.2 C39.2 C40.2 C41.2 C42.2 C43.2 C44.2 C45.2 C46.2 C47.2 C48.2 C49.2 C50.2 C51.2 C52.2 C53.2 C54.1 C55.1 C56.1 C57.1 C58.1 C59.1 C60.1 C61.2 C62.2 CN1.1 CN1.6 CN1.7 CN1.14 CN1.17 CN1.22 CN1.25 CN1.28 CN1.31 CN1.34 CN1.37 CN1.40 CN1.46 CN1.49 CN2.2 CN2.8 CN2.14 CN2.20 CN2.26 CN2.32 CN2.38 CN2.44 CN2.50 CN3.8 CN3.19 CN3.20 CN3.22 CN4.9 CN4.20 CN4.32 CN5.6 CN5.7 CN6.7 CN9.A1 CN9.A12 CN9.B1 CN9.B12 CN9.SH1 CN9.SH2 CN9.SH3 CN9.SH4 CN10.2 CN11.2 CN12.1 CN12.2 CN13.1 CN13.2 CN14.2 CN15.A1 CN15.A12 CN15.B1 CN15.B12 CN15.SH1 CN15.SH2 CN15.SH3 CN15.SH4 CN16.3 CN17.5 CN17.7 JP3.2 LD4.2 LD5.3 LD6.3 R11.1 R12.1 R14.2 R23.2 R30.2 R31.2 R38.2 R41.1 R42.1 R45.2 R46.1 R47.1 R53.1 R54.1 R59.1 SW1.0 U1.3 U2.2 U3.1 U4.2 U4.EP U5.D5 U5.D6 U5.D7 U5.D8 U5.D9 U5.F2 U5.F6 U5.F7 U5.F8 U5.F9 U5.F10 U5.F12 U5.G2 U5.G6 U5.G7 U5.G8 U5.G9 U5.G10 U5.G12 U5.H6 U5.H7 U5.H8 U5.H9 U5.H10 U5.H12 U5.J6 U5.J7 U5.J8 U5.J9 U5.J10 U5.K6 U5.K7 U5.K8 U5.K9 U5.K10 U5.L4 U5.M1 U5.M8 U5.M9 U5.N1 U6.7 U6.8 U6.9 U6.10 U6.15 U6.17 U7.2 U8.3 U9.8 U9.17 U10.8 U10.9 U11.2 U12.2 U13.2 U14.2 U15.8 U15.9 U15.10 U15.15 U15.17 U16.2 U17.2 U18.2 U19.2 X1.2 X1.4 | length 194.9
  Top Layer w0.3: B1.3@-50.3,-47.222 v1(-50.3,-46.1) -50.3,-46.059 -50.269,-46.028 U16.2@-50.269,-45.424 ; U16.2@-50.207,-45.485 U16.2@-50.269,-45.424 ; C12.1@-50.2,-44.75 -50.269,-44.819 U16.2@-50.269,-45.424 ; v1@-49.75,-24.275 v1(-49.75,-24.25) ; CN1.37@-47.855,-22.86 -46.54,-22.86 v1@-46.525,-22.875 ; B1.1@-46.2,-47.222 -45.128,-47.222 v1(-45.125,-47.225) -45.122,-47.222 B2.3@-44,-47.222 ; CN1.40@-44.855,-24.13 -44.852,-24.127 -43.577,-24.127 v1(-43.575,-24.125) ; CN1.34@-44.855,-20.32 -44.852,-20.323 -43.603,-20.323 v1(-43.6,-20.325) ; C7.1@-43,0.95 v1(-43,1.625) ; C13.1@-39.95,-44.75 -39.95,-45.363 -39.875,-45.437 -39.875,-45.485 U17.2@-39.86,-45.5 ; B2.1@-39.9,-47.222 v1(-39.9,-46.075) ; v1@-39.9,-46.1 -39.871,-46.071 -39.871,-45.511 U17.2@-39.86,-45.5 ; U17.2@-39.812,-45.5 U17.2@-39.86,-45.5 ; C14.1@-37.95,-45 -37.875,-45.075 -37.875,-45.635 -37.86,-45.65 U18.2@-37.812,-45.65 ; B3.3@-37.85,-47.25 -37.85,-46.25 -37.85,-45.665 U18.2@-37.835,-45.65 ; B3.1@-33.75,-47.25 v1(-33.75,-46.075) ; B4.3@-29.725,-47.375 B4.3@-29.6,-47.25 ; B4.1@-25.625,-47.375 B4.1@-25.5,-47.25 -25.3,-47.05 C62.2@-24.25,-47.05 ; U19.2@-24.25,-49.312 -23.663,-49.312 v1(-23.65,-49.3) ; R47.1@-22.5,-12.95 v1(-21.75,-12.95) ; v1(-18.275,-19.025) -18.263,-19.012 -17.462,-19.012 C10.1@-17.45,-19 ; v1(-17.625,-32.5) C11.1@-16.95,-32.5 ; v1(-15.5,-40.625) LD5.3@-15.5,-39.5 ; LD6.3@-12,-39.5 -12,-38.176 -11.824,-38 v1(-11.25,-38)
  Top Layer w0.4: CN1.6@-44.855,-2.54 -44.79,-2.475 v1(-42.35,-2.475)
  Top Layer w0.5: v1(-49.5,-10.15) -49.495,-10.155 -47.86,-10.155 CN1.17@-47.855,-10.16 ; v1(-49.476,-15.235) -49.471,-15.24 CN1.25@-47.855,-15.24 -47.836,-15.24 CN1.25@-47.831,-15.245 ; v1(-49.3,-19.05) CN1.31@-47.855,-19.05 ; v1(-47.875,-31.475) -47.875,-30.519 CN1.49@-47.836,-30.48 ; CN1.22@-44.879,-12.7 CN1.22@-44.855,-12.7 v1(-43.25,-12.7) ; CN1.14@-44.855,-7.62 -43.28,-7.62 v1(-43.275,-7.625) ; CN1.46@-44.845,-27.93 -44.833,-27.942 -43.308,-27.942 v1(-43.3,-27.95) ; C2.1@-39.9,0 v1(-38.75,0) ; LD4.2@-32,-38.25 v1(-32,-37.325) ; C1.1@-20.5,-3.9 -20.488,-3.888 -20.488,-2.838 v1(-20.475,-2.825) ; C6.1@-12.65,-32.5 v1(-11.644,-32.5) ; CN2.44@-10.565,-26.67 -10.562,-26.672 -9.128,-26.672 v1(-9.125,-26.675) ; CN2.38@-10.565,-22.86 -10.56,-22.855 -9.13,-22.855 v1(-9.125,-22.85) ; CN2.20@-10.565,-11.43 v1(-8.939,-11.43) ; CN2.26@-10.541,-15.24 v1(-8.92,-15.24) ; CN2.50@-10.195,-30.48 -10.151,-30.524 -10.151,-31.524 v1(-10.125,-31.55) ; CN2.32@-10.195,-19.05 v1(-8.944,-19.05) ; CN2.14@-10.195,-7.62 -7.38,-7.62 -6.406,-8.594 -5.122,-8.594 CN6.7@-5.08,-8.636 -2.989,-8.636 -1.465,-10.16 CN4.9@0,-10.16 ; CN2.8@-10.195,-3.81 -8.81,-3.81 v1(-8.775,-3.775) ; CN2.2@-10.195,0 v1(-8.775,0)
  Bottom Layer w0.15: v1(-27.85,-28.402) v1@-27.85,-28.4
  Bottom Layer w0.2: v1(-46.125,-1.875) -46.1,-1.9 -45.452,-1.9 -45.302,-2.05 -43.959,-2.05 -43.841,-2.167 -43.841,-2.809 U13.2@-43.75,-2.9 ; C60.1@-45.75,-25.95 -44.425,-25.95 -44.35,-26.025 v1(-43.575,-26.025) ; v1(-34.074,-24.751) C51.2@-33.45,-24.75 ; v1(-34.05,-25.55) C52.2@-33.45,-25.55 C53.2@-33.45,-26.8 ; v1(-31.225,-18.3) C49.2@-30.6,-18.3 ; C48.2@-29.375,-18.3 v1(-28.75,-18.3) ; v1(-29.175,-26.475) U5.D9@-28.85,-26.15 ; v1(-29.175,-25.825) U5.D8@-28.85,-25.5 ; v1(-29.175,-24.525) U5.D7@-28.85,-24.85 ; v1(-29.175,-23.875) U5.D6@-28.85,-24.2 ; v1(-29.175,-23.225) U5.D5@-28.85,-23.55 ; C47.2@-28.125,-18.3 C47.2@-28.1,-18.275 ; v1(-27.875,-23.875) U5.F6@-27.55,-24.2 ; v1(-27.875,-21.275) U5.F2@-27.55,-21.6 ; v1@-27.85,-28.4 U5.F12@-27.55,-28.1 ; v1@-27.475,-18.275 v1(-27.45,-18.25) v1@-27.425,-18.225 ; X1.4@-27.425,-17.05 X1.4@-27.2,-17.275 ; v1(-27.225,-28.425) U5.G12@-26.9,-28.1 ; U5.G2@-26.9,-21.6 v1(-26.575,-21.275) ; U5.H12@-26.237,-28.113 v1(-25.925,-28.425) ; v1(-26.075,-15.5) X1.2@-26.075,-16.225 -26,-16.3 X1.2@-25.913,-16.3 ; v1(-25.675,-18.275) v1@-25.65,-18.3 ; v1(-24.625,-27.125) U5.K10@-24.95,-26.8 ; v1(-24.625,-23.875) U5.K6@-24.95,-24.2 ; U5.L4@-24.3,-22.9 v1(-23.975,-22.575) ; U5.M9@-23.65,-26.15 v1(-23.325,-26.475) ; U5.M8@-23.65,-25.5 v1(-23.325,-25.825) ; U5.M1@-23.65,-20.95 v1(-23.325,-20.625) U5.N1@-23,-20.95 ; C45.2@-22.5,-18.3 v1(-22.5,-17.625) ; C44.2@-21.5,-18.3 v1(-21.5,-17.625) ; U5.F7@-27.55,-24.85 v1(-27.225,-24.525) ; U5.F7@-27.55,-24.85 v1(-27.225,-25.175) ; U5.F7@-27.55,-24.85 v1(-27.875,-24.525) U5.F6@-27.55,-24.2 ; U5.F6@-27.55,-24.2 v1(-27.225,-23.875) U5.G6@-26.9,-24.2 ; U5.F6@-27.55,-24.2 v1(-27.225,-24.525) ; v1(-27.225,-26.475) v1(-26.575,-25.825) ; v1(-27.225,-26.475) U5.G10@-26.9,-26.8 ; v1(-27.225,-26.475) U5.F10@-27.55,-26.8 v1(-27.225,-27.125) U5.G10@-26.9,-26.8 ; v1(-27.225,-26.475) U5.F9@-27.55,-26.15 v1(-27.225,-25.825) ; v1(-27.225,-25.825) U5.F8@-27.55,-25.5 v1(-27.225,-25.175) ; v1(-27.225,-25.825) U5.G8@-26.9,-25.5 ; v1(-27.225,-25.825) U5.G9@-26.9,-26.15 v1(-26.575,-26.475) ; v1(-27.225,-25.175) v1(-26.575,-24.525) ; v1(-27.225,-25.175) U5.G8@-26.9,-25.5 ; v1(-27.225,-24.525) U5.G6@-26.9,-24.2 ; v1(-27.225,-24.525) U5.G7@-26.9,-24.85 v1(-26.575,-25.175) ; U5.G10@-26.9,-26.8 v1(-26.575,-27.125) U5.H10@-26.25,-26.8 ; U5.G10@-26.9,-26.8 v1(-26.575,-26.475) ; U5.G8@-26.9,-25.5 v1(-26.575,-25.175) ; U5.G8@-26.9,-25.5 v1(-26.575,-25.825) ; U5.G6@-26.9,-24.2 v1(-26.575,-24.525) ; U5.G6@-26.9,-24.2 v1(-26.575,-23.875) U5.H6@-26.25,-24.2 ; v1(-26.575,-26.475) U5.H9@-26.25,-26.15 ; v1(-26.575,-26.475) U5.H10@-26.25,-26.8 ; v1(-26.575,-25.825) U5.H8@-26.25,-25.5 ; v1(-26.575,-25.825) U5.H9@-26.25,-26.15 ; v1(-26.575,-25.175) U5.H7@-26.25,-24.85 ; v1(-26.575,-25.175) U5.H8@-26.25,-25.5 ; v1(-26.575,-24.525) U5.H6@-26.25,-24.2 ; v1(-26.575,-24.525) U5.H7@-26.25,-24.85 ; U5.H10@-26.25,-26.8 v1(-25.925,-26.475) ; U5.H10@-26.25,-26.8 v1(-25.925,-27.125) U5.J10@-25.6,-26.8 ; U5.H9@-26.25,-26.15 v1(-25.925,-25.825) ; U5.H9@-26.25,-26.15 v1(-25.925,-26.475) ; U5.H8@-26.25,-25.5 v1(-25.925,-25.825) ; U5.H8@-26.25,-25.5 v1(-25.925,-25.175) ; U5.H7@-26.25,-24.85 v1(-25.925,-24.525) ; U5.H7@-26.25,-24.85 v1(-25.925,-25.175) ; U5.H6@-26.25,-24.2 v1(-25.925,-23.875) U5.J6@-25.6,-24.2 ; U5.H6@-26.25,-24.2 v1(-25.925,-24.525) ; v1(-25.925,-26.475) v1(-25.275,-25.825) ; v1(-25.925,-26.475) U5.J10@-25.6,-26.8 ; v1(-25.925,-25.825) U5.J9@-25.6,-26.15 v1(-25.275,-26.475) ; v1(-25.925,-25.825) U5.J8@-25.6,-25.5 ; v1(-25.925,-25.175) v1(-25.275,-24.525) ; v1(-25.925,-25.175) U5.J8@-25.6,-25.5 ; v1(-25.925,-24.525) U5.J6@-25.6,-24.2 ; v1(-25.925,-24.525) U5.J7@-25.6,-24.85 v1(-25.275,-25.175) ; U5.J10@-25.6,-26.8 v1(-25.275,-27.125) U5.K10@-24.95,-26.8 ; U5.J10@-25.6,-26.8 v1(-25.275,-26.475) ; U5.J8@-25.6,-25.5 v1(-25.275,-25.825) ; U5.J8@-25.6,-25.5 v1(-25.275,-25.175) ; U5.J6@-25.6,-24.2 v1(-25.275,-24.525) ; U5.J6@-25.6,-24.2 v1(-25.275,-23.875) U5.K6@-24.95,-24.2 ; v1(-25.275,-26.475) U5.K9@-24.95,-26.15 ; v1(-25.275,-26.475) U5.K10@-24.95,-26.8 ; v1(-25.275,-25.825) U5.K8@-24.95,-25.5 ; v1(-25.275,-25.825) U5.K9@-24.95,-26.15 ; v1(-25.275,-25.175) U5.K8@-24.95,-25.5 ; v1(-25.275,-25.175) U5.K7@-24.95,-24.85 ; v1(-25.275,-24.525) U5.K6@-24.95,-24.2 ; v1(-25.275,-24.525) U5.K7@-24.95,-24.85 ; U5.K10@-24.95,-26.8 v1(-24.625,-26.475) U5.K9@-24.95,-26.15 ; U5.K9@-24.95,-26.15 v1(-24.625,-25.825) U5.K8@-24.95,-25.5 ; U5.K8@-24.95,-25.5 v1(-24.625,-25.175) U5.K7@-24.95,-24.85 ; U5.K7@-24.95,-24.85 v1(-24.625,-24.525) U5.K6@-24.95,-24.2
  Bottom Layer w0.25: U14.2@-44.75,1.35 v1(-44.75,2.35) ; U1.3@-12.25,-39.6 -11.775,-39.6 -11.579,-39.796 -11.004,-39.796 R11.1@-11,-39.8
  Bottom Layer w0.254: R59.1@-35.75,-23.05 v1(-35.75,-22.375)
  Bottom Layer w0.3: U15.8@-50.7,-24.5 -50.95,-24.5 -50.95,-24 -50.875,-24 v1(-50.875,-23.3) -50.25,-23.3 U15.10@-50.25,-23.05 ; SW1.0@-50.35,-47.409 -50.3,-47.359 v1(-50.3,-46.1) ; v1(-49.75,-24.25) U15.17@-49,-24.25 ; U15.15@-47.75,-23.05 -47.75,-23.075 -47.225,-23.075 -47.025,-22.875 v1(-46.5,-22.875) -46.248,-22.623 -45.823,-22.623 C61.2@-45.75,-22.55 ; v1(-42.575,-33.2) R42.1@-41.75,-33.2 ; R41.1@-41.25,-18.45 v1(-40.5,-18.45) ; v1@-40.499,-26.5 -40.249,-26.25 U6.10@-39.7,-26.25 ; v1(-40.025,-12.675) -40.024,-12.676 -39.671,-12.676 -39.554,-12.793 -39.13,-12.793 -39.123,-12.8 C31.2@-39,-12.8 ; C25.2@-39.95,-21.75 -39.95,-22.624 -39.725,-22.849 v1(-39.725,-22.875) -39.7,-22.9 U6.15@-39.7,-23.75 ; U6.9@-38.75,-26.7 -38.75,-27.475 v1(-38.475,-27.75) -38.475,-27.73 -38.25,-27.505 U6.8@-38.25,-26.7 ; U10.8@-38.65,-30.75 v1(-38.651,-30.149) ; U9.8@-38.25,-18.2 -38.25,-18.425 v1(-37.525,-18.425) ; C30.1@-37.925,-12.75 -37.87,-12.695 -37.87,-12.651 -37.694,-12.475 v1(-37.125,-12.475) ; U6.7@-37.3,-26.25 -36.775,-26.25 v1(-36.5,-26.525) ; C24.1@-37.05,-21.75 v1(-36.425,-21.75) ; C36.1@-35.75,-29.8 v1(-35.75,-29.075) ; R46.1@-34.75,-29.8 v1(-34.75,-29.075) ; v1(-34.05,-22.75) C50.2@-33.45,-22.75 ; v1(-31.1,-33) -31.075,-32.975 -30.525,-32.975 C57.1@-30.5,-32.95 ; v1(-30.907,-44.563) -30.88,-44.59 CN15.B1@-30.26,-44.59 ; v1(-30.511,-42.119) -30.51,-42.12 CN15.A12@-30.51,-42.89 ; C27.2@-30.5,-37.55 v1(-30.5,-36.825) ; R23.2@-29.5,-39.55 v1(-29.5,-38.75) ; v1(-28.85,-33) -28.825,-32.975 -28.275,-32.975 C40.2@-28.25,-32.95 ; v1(-27.625,-32.975) -27.613,-32.963 -27.012,-32.963 C39.2@-27,-32.95 ; C37.2@-26.175,-32.95 -26.163,-32.962 -25.587,-32.962 v1(-25.575,-32.975) ; R14.2@-26,-39.55 v1(-26,-38.75) ; CN15.A1@-25.01,-43.09 CN15.A1@-25.01,-42.905 ; CN15.A1@-25.01,-42.89 -25.01,-42.205 v1(-25,-42.195) ; C26.2@-25,-37.55 v1(-25,-36.825) ; v1(-24.825,-33.525) R30.2@-24.825,-32.975 ; CN15.B12@-24.76,-44.59 -24.76,-44.752 CN15.SH1@-23.678,-44.752 ; v1(-23.875,-33.525) C33.1@-23.875,-32.95 ; C33.1@-23.825,-32.975 -23.8,-32.95 C38.2@-23,-32.95 ; C56.1@-19.05,-28.4 v1(-18.275,-28.4) ; C41.2@-19.05,-27.25 v1(-18.275,-27.25) ; C42.2@-19.05,-26.1 v1(-18.275,-26.1) ; C43.2@-19.05,-25.25 v1(-18.275,-25.25) ; R38.2@-19.05,-24 v1(-18.275,-24) ; R31.2@-19.05,-20.9 v1(-19.05,-20.125) ; U11.2@-18.65,-36.5 -17.825,-36.5 -17.726,-36.599 -17.713,-36.612 -17.138,-36.612 -17.05,-36.7 C55.1@-17,-36.7 v1(-17,-37.5) ; v1(-16.9,-40.625) C54.1@-16.9,-39.5 ; v1(-15.887,-44.563) -15.86,-44.59 CN9.B1@-15.24,-44.59 ; v1(-15.491,-42.119) v1(-15.491,-42.119) CN9.A12@-15.49,-42.89 ; v1(-14.75,-38) -14.75,-38.875 -14.5,-39.125 R12.1@-14.5,-39.8 ; v1(-11.25,-38) -11.25,-38.75 -11,-39 R11.1@-11,-39.8 ; CN9.A1@-9.99,-43.09 CN9.A1@-9.99,-42.905 ; CN9.A1@-9.99,-42.89 -9.99,-42.205 v1(-9.98,-42.195) ; CN9.B12@-9.74,-44.59 -9.74,-44.752 -8.658,-44.752 CN9.SH1@-8.61,-44.8
  Bottom Layer w0.4: R45.2@-41.75,-29.8 v1(-41.75,-29.125) ; C59.1@-38.3,-35.25 v1(-37.375,-35.25) ; C58.1@-38.05,-41 v1(-37.375,-41)
  Bottom Layer w0.5: v1(-56.75,0.25) R54.1@-55.95,0.25 ; v1(-54.525,-2.25) CN17.7@-52.532,-2.25 ; v1(-54.5,-3.525) -54.498,-3.522 -52.534,-3.522 CN17.5@-52.532,-3.52 ; SW1.0@-50.35,-49.709 -49.166,-49.709 v1(-49.15,-49.725) ; SW1.0@-42.85,-49.709 -41.659,-49.709 v1(-41.65,-49.7) ; C22.1@-34.55,-8.75 v1(-33.55,-8.75) ; C20.1@-34.55,-4.25 v1(-33.675,-4.25) ; v1(-34.25,-6.5) U4.2@-32.95,-6.5 ; C21.1@-33.65,-10.25 v1(-32.5,-10.25) ; C19.1@-33.65,-2.75 v1(-32.65,-2.75) ; v1(-30.15,-8.275) -28.7,-8.275 U3.1@-28.675,-8.3 ; C18.1@-29,0.2 v1(-29,1.05) ; v1(-28.25,-11.225) -28.225,-11.25 C17.2@-26.875,-11.25 ; C16.2@-24.125,-0.75 v1@-22.775,-0.75
  other v1: -22.25,-49.75 -38.938,-49.709 -36.195,-49.709 -32.715,-49.709 -17.442,-49.709 -7.747,-49.709 -6.579,-48.559 -52.603,-47.988 -61.25,-47.75 4.826,-47.523 -63.5,-45.72 5.08,-44.425 -63.5,-43.129 5.08,-41.91 -63.5,-40.64 5.08,-39.421 -63.5,-38.1 5.08,-36.825 -63.5,-35.56 5.08,-34.29 -63.5,-33.02 -38.2,-32.95 -37.2,-32.95 -37.75,-32.1 5.08,-31.767 -37.75,-31.5 -20.175,-30.9 -37.75,-30.85 -63.5,-30.455 5.08,-29.21 -63.5,-27.94 5.08,-26.695 -40.5,-26.5 -38.5,-25.75 -63.5,-25.425 -38.5,-25 -38.5,-24.25 5.08,-24.13 -63.5,-22.85 5.08,-21.539 -31.525,-21.3 -32.3,-20.575 -63.5,-20.32 -27.35,-19.9 -25.875,-19.875 -27.425,-19.175 -25.675,-19.15 5.08,-19.05 -63.5,-17.78 -31.625,-17.7 -38.5,-17.25 -29.175,-17.2 -24.3,-16.95 -38.5,-16.5 5.08,-16.485 -24.3,-16.275 -29.15,-16.25 -38.5,-15.75 -28.35,-15.5 -27.575,-15.5 -26.75,-15.5 -25.2,-15.5 -63.5,-15.215 5.08,-13.945 -63.5,-12.7 5.08,-11.455 -63.5,-10.16 5.08,-8.859 -63.5,-7.62 -34.25,-7.4 4.826,-6.35 -34.25,-5.675 -63.5,-5.08 4.826,-3.757 -63.5,-2.54 4.826,-1.225 -22.75,-0.775 -63.5,0 4.85,1.15 -63.5,2.525 4.825,3.875 -56,5.25 -53.46,5.25 -50.92,5.25 -48.38,5.25 -45.865,5.25 -43.376,5.25 -40.709,5.25 -38.22,5.25 -35.641,5.25 -33.14,5.25 -30.625,5.25 -28.109,5.25 -25.52,5.25 -22.98,5.25 -20.44,5.25 -17.9,5.25 -15.36,5.25 -12.82,5.25 -10.28,5.25 -7.74,5.25 -5.2,5.25 -2.711,5.25 1.524,5.588
GNDDetect: CN17.11 R54.2 | length 2.6
  Bottom Layer w0.5: R54.2@-55.05,0.25 -55.05,0.285 -55.045,0.29 CN17.11@-52.532,0.29
GPIO0: CN1.3 CN3.1 | length 15.1
  Top Layer w0.2: CN3.1@-60.96,0 -59.21,1.75 -53,1.75 -49.98,-1.27 CN1.3@-47.855,-1.27
GPIO1: CN1.5 CN3.3 | length 14.2
  Top Layer w0.2: CN3.3@-60.96,-2.54 -59.67,-1.25 -52,-1.25 -50.71,-2.54 CN1.5@-47.855,-2.54
GPIO2: CN1.8 CN3.2 SB23.1 | length 19.3
  Top Layer w0.2: CN3.2@-58.42,0 -57.57,-0.85 -51.75,-0.85 -50.7,-1.9 -46.75,-1.9 -46.2,-2.45 -46.2,-3.025 -45.663,-3.562 -45.103,-3.562 CN1.8@-44.855,-3.81 -42.915,-3.81 v1(-42.375,-4.35)
  Bottom Layer w0.2: v1(-42.375,-4.35) -42.025,-4 SB23.1@-41.45,-4
GPIO3/BOOT0: CN1.9 CN3.7 SB28.1 | length 21
  Top Layer w0.15: CN1.9@-47.855,-5.08 -46.795,-5.08 -46.175,-5.7 -43.375,-5.7 v1(-43.35,-5.675)
  Top Layer w0.2: CN3.7@-60.96,-7.62 -59.74,-6.4 -50.35,-6.4 -49.03,-5.08 CN1.9@-47.855,-5.08
  Bottom Layer w0.15: v1(-43.35,-5.675) -43,-5.675 -42.575,-5.25 SB28.1@-41.45,-5.25
GPIO4: CN1.10 CN3.4 | length 14.6
  Top Layer w0.2: CN3.4@-58.42,-2.54 -56.125,-2.54 -55.79,-2.875 -52.7,-2.875 -51.125,-4.45 -46,-4.45 -45.628,-4.822 -45.628,-4.832 -45.38,-5.08 CN1.10@-44.855,-5.08
GPIO5/JTMS/SWDIO: CN1.13 CN3.9 SB17.1 | length 23.8
  Top Layer w0.15: CN1.13@-47.855,-7.62 -47.7,-7.775 -46.389,-7.775 -46.036,-7.422 -46.036,-7.211 -45.775,-6.95 -43.3,-6.95 v1(-42.625,-7.625)
  Top Layer w0.2: CN3.9@-60.96,-10.16 -59.725,-8.925 -55.7,-8.925 -53.5,-6.725 -50.075,-6.725 -49.18,-7.62 CN1.13@-47.855,-7.62 CN1.13@-47.33,-7.62
  Bottom Layer w0.15: v1(-42.625,-7.625) -42.625,-7.888 -42.625,-8.675 -42.3,-9 SB17.1@-41.45,-9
